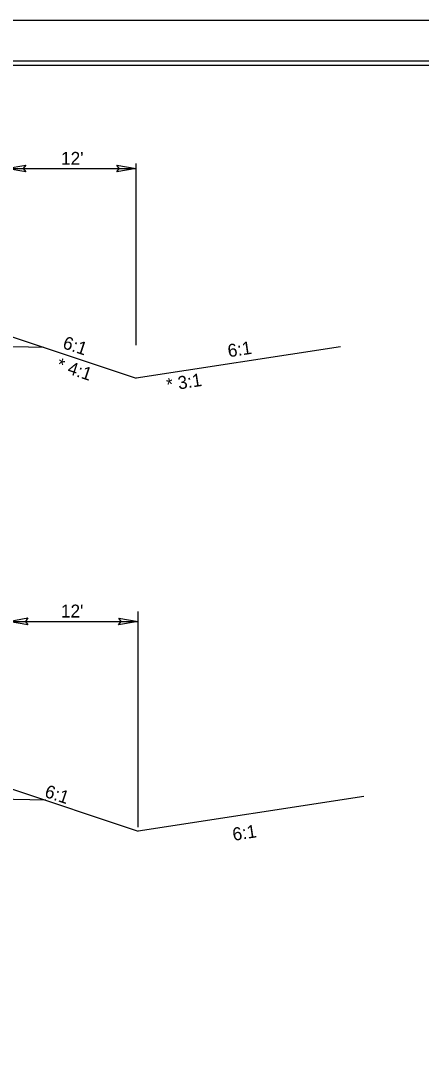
# Model space of a CAD drawing. Extents: x 1718167 to 1721223, y 797898 to 799800.
# Drawn here: x 1719954 to 1720176, y 798557 to 799124 of the extents above; entities that cross this region are included whole.
import ezdxf

# ---------------------------------------------------------------- set-up
doc = ezdxf.new("R2010")
doc.units = 0
for name, color, linetype in [('Old_Level_1', 7, 'Continuous'), ('Prop Dimension Text', 7, 'Continuous'), ('Prop Terminator CELL', 7, 'Continuous'), ('Sheet Cutting Line CELL', 7, 'Continuous'), ('Sheet Plot Border Inside CELL', 7, 'Continuous'), ('Sheet Plot Border Outside CELL', 7, 'Continuous'), ('Sheet Typical CELL', 7, 'Continuous'), ('Typical Slope Point Local CELL', 7, 'Continuous')]:
    doc.layers.add(name, color=color, linetype=linetype)

msp = doc.modelspace()

# ---------------------------------------------------------------- linework, layer by layer
at = {"layer": 'Old_Level_1'}
for p, q in [((1719885.72, 799042.38), (1720017.84, 799042.36)), ((1720017.82, 798944.46), (1720017.85, 799045.15)), ((1719945.7, 798950.2), (1720017.82, 798926.14)), ((1720018.89, 798677.52), (1720018.92, 798796.91)), ((1719946.92, 798791.41), (1720018.92, 798791.4)), ((1719946.98, 798699.23), (1720018.96, 798675.22))]:
    msp.add_line(p, q, dxfattribs=at)
at = {"layer": 'Prop Terminator CELL'}
for points in [[(1719956.52, 799040.51), (1719945.72, 799042.37), (1719956.58, 799044.29), (1719955.2, 799042.37)], [(1720007.04, 799044.22), (1720017.84, 799042.36), (1720006.98, 799040.44), (1720008.36, 799042.36)], [(1719957.72, 798789.55), (1719946.92, 798791.41), (1719957.78, 798793.33), (1719956.4, 798791.41)], [(1720008.12, 798793.26), (1720018.92, 798791.4), (1720008.06, 798789.48), (1720009.44, 798791.4)]]:
    msp.add_lwpolyline(points, close=True, dxfattribs=at)
at = {"layer": 'Sheet Cutting Line CELL'}
msp.add_line((1720550, 799124.37), (1718866, 799124.37), dxfattribs=at)
at = {"layer": 'Sheet Plot Border Inside CELL'}
msp.add_lwpolyline([(1720545.5, 799101.92), (1718879, 799101.92), (1718879, 798046.82), (1720545.5, 798046.82)], close=True, dxfattribs=at)
at = {"layer": 'Sheet Plot Border Outside CELL'}
msp.add_lwpolyline([(1720550, 799124.37), (1718866, 799124.37), (1718866, 798024.37), (1720550, 798024.37)], close=True, dxfattribs=at)
at = {"layer": 'Sheet Typical CELL'}
msp.add_lwpolyline([(1720533, 799099.37), (1719033, 799099.37), (1719033, 798049.37), (1720533, 798049.37)], close=True, dxfattribs=at)
at = {"layer": 'Typical Slope Point Local CELL'}
for p, q in [((1719966.5, 798943.26), (1719931.73, 798943.98)), ((1720131.06, 798943.49), (1720017.82, 798926.14)), ((1719967.76, 798692.3), (1719932.93, 798693.02)), ((1720143.96, 798694.37), (1720018.96, 798675.22))]:
    msp.add_line(p, q, dxfattribs=at)

# ---------------------------------------------------------------- texts
at = {"layer": 'Old_Level_1'}
for p in [(1719976.09, 799044.41), (1719976.03, 798793.59)]:
    msp.add_text("12'", height=7.161, rotation=359.988, dxfattribs=at).set_placement(p)
at = {"layer": 'Prop Dimension Text'}
for s, p in [('6:1', (1719976.53, 798942.92)), ('* 4:1', (1719973.12, 798930.89)), ('6:1', (1719966.5, 798694.34))]:
    msp.add_text(s, height=7.161, rotation=341.5531, dxfattribs=at).set_placement(p)
at = {"layer": 'Typical Slope Point Local CELL'}
for s, p in [('6:1', (1720069.08, 798937.73)), ('* 3:1', (1720035.1, 798918.95)), ('6:1', (1720071.75, 798669.84))]:
    msp.add_text(s, height=7.161, rotation=8.7105, dxfattribs=at).set_placement(p)

doc.saveas('drawing.dxf')
